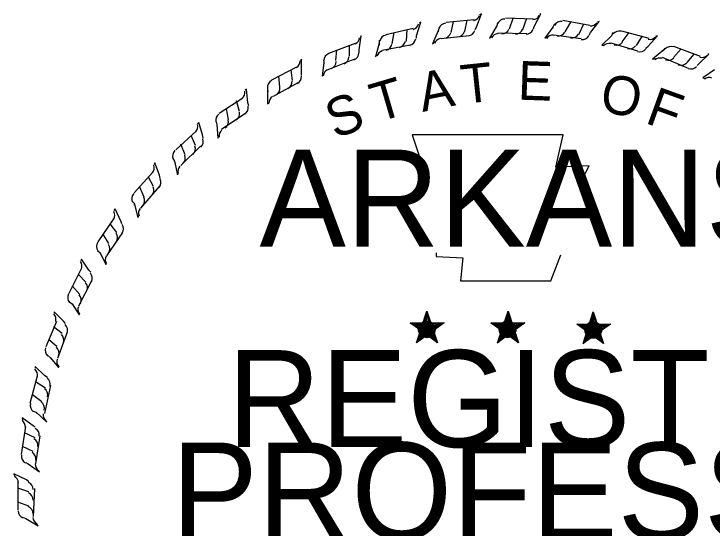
# Model space of a CAD drawing. Extents: x -900 to -62, y -12423 to -11428.
# Drawn here: x -141.81 to -114.78, y -12212.6 to -12192.71 of the extents above; entities that cross this region are included whole.
import ezdxf

# ---------------------------------------------------------------- set-up
doc = ezdxf.new("R2010")
doc.units = 0
doc.layers.add('Level 1', color=7, linetype='Continuous')

msp = doc.modelspace()

# ---------------------------------------------------------------- linework, layer by layer
at = {"layer": 'Level 1'}
for p, q in [((-123.902, -12193.218), (-123.71, -12192.714)), ((-123.71, -12192.714), (-123.782, -12192.762)), ((-121.67, -12193.194), (-121.406, -12192.714)), ((-121.406, -12192.714), (-121.454, -12192.738)), ((-125.078, -12193.026), (-123.998, -12192.93)), ((-124.886, -12193.434), (-124.79, -12193.002)), ((-124.358, -12193.386), (-124.262, -12192.954)), ((-122.774, -12192.858), (-121.694, -12192.906)), ((-122.63, -12193.29), (-122.486, -12192.882)), ((-122.102, -12193.314), (-121.958, -12192.882)), ((-120.566, -12192.954), (-119.51, -12193.146)), ((-119.486, -12193.434), (-119.15, -12193.002)), ((-119.15, -12193.002), (-119.222, -12193.026)), ((-127.406, -12193.506), (-126.35, -12193.266)), ((-126.23, -12193.554), (-126.062, -12193.026)), ((-126.062, -12193.026), (-126.11, -12193.074)), ((-125.342, -12193.242), (-125.39, -12193.362)), ((-123.95, -12193.314), (-123.902, -12193.218)), ((-123.11, -12193.17), (-123.398, -12193.65)), ((-123.11, -12193.17), (-123.134, -12193.194)), ((-123.086, -12193.05), (-123.11, -12193.17)), ((-121.694, -12193.29), (-121.67, -12193.194)), ((-120.95, -12193.218), (-121.262, -12193.65)), ((-120.878, -12193.098), (-120.95, -12193.218)), ((-120.95, -12193.218), (-120.95, -12193.266)), ((-120.47, -12193.41), (-120.254, -12193.026)), ((-119.942, -12193.506), (-119.75, -12193.098)), ((-127.166, -12193.866), (-127.094, -12193.434)), ((-126.614, -12193.77), (-126.59, -12193.314)), ((-125.39, -12193.362), (-125.606, -12193.866)), ((-125.39, -12193.362), (-125.39, -12193.41)), ((-121.958, -12193.482), (-123.062, -12193.458)), ((-119.846, -12193.674), (-120.926, -12193.53)), ((-119.534, -12193.53), (-119.486, -12193.434)), ((-118.622, -12193.434), (-118.67, -12193.554)), ((-118.286, -12193.362), (-117.23, -12193.65)), ((-118.262, -12193.794), (-117.998, -12193.434)), ((-128.438, -12194.106), (-128.366, -12193.554)), ((-128.366, -12193.554), (-128.39, -12193.626)), ((-127.67, -12193.722), (-127.67, -12193.842)), ((-126.23, -12193.65), (-126.23, -12193.554)), ((-125.606, -12193.866), (-125.51, -12193.794)), ((-124.19, -12193.554), (-125.27, -12193.674)), ((-123.398, -12193.65), (-123.302, -12193.578)), ((-121.262, -12193.65), (-121.19, -12193.602)), ((-118.67, -12193.554), (-119.054, -12193.914)), ((-118.67, -12193.554), (-118.694, -12193.554)), ((-117.71, -12193.938), (-117.47, -12193.554)), ((-117.254, -12193.962), (-116.894, -12193.554)), ((-116.894, -12193.554), (-116.966, -12193.578)), ((-129.614, -12194.226), (-128.582, -12193.842)), ((-128.822, -12194.346), (-128.822, -12193.914)), ((-127.67, -12193.842), (-127.814, -12194.37)), ((-127.67, -12193.842), (-127.67, -12193.914)), ((-126.47, -12193.914), (-127.55, -12194.13)), ((-119.054, -12193.914), (-118.958, -12193.914)), ((-117.662, -12194.154), (-118.694, -12193.842)), ((-117.35, -12194.034), (-117.254, -12193.962)), ((-116.606, -12194.034), (-116.654, -12194.106)), ((-116.27, -12193.962), (-115.238, -12194.346)), ((-116.27, -12194.394), (-115.982, -12194.058)), ((-129.35, -12194.514), (-129.302, -12194.106)), ((-128.438, -12194.202), (-128.438, -12194.106)), ((-127.814, -12194.37), (-127.742, -12194.274)), ((-116.654, -12194.106), (-117.086, -12194.466)), ((-116.654, -12194.106), (-116.702, -12194.154)), ((-115.742, -12194.586), (-115.478, -12194.274)), ((-115.286, -12194.634), (-114.902, -12194.274)), ((-114.902, -12194.274), (-114.95, -12194.274)), ((-130.67, -12194.466), (-130.718, -12194.514)), ((-130.67, -12194.994), (-130.67, -12194.466)), ((-129.806, -12194.586), (-129.878, -12195.114)), ((-129.83, -12194.49), (-129.806, -12194.586)), ((-129.806, -12194.586), (-129.83, -12194.634)), ((-128.63, -12194.466), (-129.662, -12194.874)), ((-117.086, -12194.466), (-116.99, -12194.442)), ((-115.694, -12194.826), (-116.702, -12194.394)), ((-131.822, -12195.258), (-130.862, -12194.754)), ((-131.03, -12195.282), (-131.078, -12194.874)), ((-115.358, -12194.706), (-115.286, -12194.634)), ((-114.686, -12194.874), (-115.142, -12195.186)), ((-131.51, -12195.546), (-131.558, -12195.114)), ((-130.67, -12195.09), (-130.67, -12194.994)), ((-129.878, -12195.114), (-129.83, -12195.066)), ((-130.814, -12195.378), (-131.774, -12195.906)), ((-115.142, -12195.186), (-115.046, -12195.21)), ((-132.806, -12195.618), (-132.854, -12195.666)), ((-132.758, -12196.146), (-132.806, -12195.618)), ((-131.99, -12195.546), (-131.99, -12195.666)), ((-131.99, -12195.666), (-131.99, -12196.194)), ((-131.99, -12195.666), (-131.966, -12195.714)), ((-133.862, -12196.554), (-132.95, -12195.954)), ((-133.07, -12196.482), (-133.19, -12196.074)), ((-132.71, -12196.266), (-132.758, -12196.146)), ((-131.99, -12196.194), (-131.942, -12196.146)), ((-133.502, -12196.794), (-133.574, -12196.386)), ((-132.83, -12196.554), (-133.766, -12197.178)), ((-134.654, -12196.914), (-134.702, -12196.962)), ((-134.51, -12197.394), (-134.654, -12196.914)), ((-133.982, -12196.89), (-133.958, -12196.986)), ((-133.958, -12196.986), (-133.91, -12197.514)), ((-133.958, -12196.986), (-133.958, -12197.034)), ((-135.542, -12197.97), (-134.75, -12197.25)), ((-134.774, -12197.802), (-134.942, -12197.418)), ((-134.486, -12197.514), (-134.51, -12197.394)), ((-133.91, -12197.514), (-133.862, -12197.418)), ((-135.182, -12198.162), (-135.35, -12197.754)), ((-134.582, -12197.826), (-135.35, -12198.57)), ((-135.662, -12198.306), (-135.59, -12198.402)), ((-135.59, -12198.402), (-135.47, -12198.93)), ((-135.59, -12198.402), (-135.59, -12198.45)), ((-136.358, -12198.474), (-136.382, -12198.546)), ((-136.166, -12198.954), (-136.358, -12198.474)), ((-137.15, -12199.626), (-136.43, -12198.834)), ((-135.47, -12198.93), (-135.446, -12198.834)), ((-136.406, -12199.386), (-136.598, -12199.026)), ((-136.142, -12199.074), (-136.166, -12198.954)), ((-136.766, -12199.794), (-136.934, -12199.41)), ((-136.19, -12199.386), (-136.91, -12200.226)), ((-137.222, -12199.962), (-137.15, -12200.034)), ((-137.894, -12200.25), (-137.942, -12200.322)), ((-137.654, -12200.754), (-137.894, -12200.25)), ((-137.15, -12200.034), (-137.006, -12200.586)), ((-137.15, -12200.034), (-137.15, -12200.106)), ((-137.006, -12200.586), (-136.958, -12200.49)), ((-138.542, -12201.522), (-137.942, -12200.634)), ((-137.822, -12201.162), (-138.086, -12200.826)), ((-137.63, -12200.826), (-137.654, -12200.754)), ((-138.134, -12201.594), (-138.35, -12201.234)), ((-137.606, -12201.162), (-138.23, -12202.074)), ((-138.566, -12201.858), (-138.47, -12201.954)), ((-139.19, -12202.194), (-139.214, -12202.266)), ((-138.902, -12202.626), (-139.19, -12202.194)), ((-138.47, -12201.954), (-138.254, -12202.41)), ((-138.47, -12201.954), (-138.47, -12201.978)), ((-138.254, -12202.41), (-138.23, -12202.314)), ((-139.67, -12203.514), (-139.19, -12202.554)), ((-138.83, -12202.698), (-138.902, -12202.626)), ((-139.022, -12203.082), (-139.31, -12202.794)), ((-139.262, -12203.562), (-139.55, -12203.226)), ((-138.806, -12203.034), (-139.31, -12204.018)), ((-139.67, -12203.85), (-139.55, -12203.922)), ((-139.55, -12203.922), (-139.286, -12204.354)), ((-139.55, -12203.922), (-139.55, -12203.97)), ((-139.886, -12204.594), (-140.246, -12204.234)), ((-140.246, -12204.234), (-140.246, -12204.306)), ((-139.286, -12204.354), (-139.262, -12204.282)), ((-125.822, -12204.21), (-125.918, -12204.666)), ((-125.822, -12204.21), (-125.87, -12204.666)), ((-125.822, -12204.21), (-125.846, -12204.666)), ((-125.822, -12204.882), (-125.822, -12204.21)), ((-125.822, -12204.21), (-125.702, -12204.666)), ((-125.822, -12204.21), (-125.726, -12204.666)), ((-125.822, -12204.21), (-125.75, -12204.666)), ((-122.678, -12204.21), (-122.798, -12204.666)), ((-122.678, -12204.21), (-122.75, -12204.666)), ((-122.678, -12204.21), (-122.726, -12204.666)), ((-122.678, -12204.882), (-122.678, -12204.21)), ((-122.678, -12204.21), (-122.558, -12204.666)), ((-122.678, -12204.21), (-122.582, -12204.666)), ((-122.678, -12204.21), (-122.63, -12204.666)), ((-119.39, -12204.234), (-119.486, -12204.69)), ((-119.39, -12204.234), (-119.462, -12204.69)), ((-119.39, -12204.906), (-119.39, -12204.234)), ((-119.39, -12204.234), (-119.246, -12204.69)), ((-119.39, -12204.234), (-119.27, -12204.69)), ((-119.39, -12204.234), (-119.342, -12204.69)), ((-119.39, -12204.234), (-119.39, -12204.69)), ((-140.558, -12205.578), (-140.15, -12204.594)), ((-139.814, -12204.69), (-139.886, -12204.594)), ((-139.934, -12205.074), (-140.27, -12204.81)), ((-126.47, -12204.666), (-125.822, -12204.882)), ((-126.47, -12204.666), (-125.99, -12204.714)), ((-126.47, -12204.666), (-125.99, -12204.762)), ((-126.47, -12204.666), (-125.99, -12204.786)), ((-126.47, -12204.666), (-126.014, -12204.858)), ((-126.47, -12204.666), (-126.014, -12204.906)), ((-126.47, -12204.666), (-126.014, -12204.954)), ((-126.23, -12205.434), (-125.822, -12204.882)), ((-125.15, -12204.666), (-125.822, -12204.882)), ((-125.414, -12205.434), (-125.822, -12204.882)), ((-125.15, -12204.666), (-125.75, -12204.714)), ((-125.15, -12204.666), (-125.702, -12204.786)), ((-125.15, -12204.666), (-125.702, -12204.81)), ((-125.15, -12204.666), (-125.582, -12204.834)), ((-125.15, -12204.666), (-125.534, -12204.858)), ((-125.15, -12204.666), (-125.51, -12204.906)), ((-123.35, -12204.666), (-122.678, -12204.882)), ((-123.35, -12204.666), (-122.87, -12204.714)), ((-123.35, -12204.666), (-122.87, -12204.762)), ((-123.35, -12204.666), (-122.87, -12204.786)), ((-123.35, -12204.666), (-122.87, -12204.858)), ((-123.35, -12204.666), (-122.894, -12204.906)), ((-123.35, -12204.666), (-122.894, -12204.954)), ((-123.086, -12205.434), (-122.678, -12204.882)), ((-122.03, -12204.666), (-122.678, -12204.882)), ((-122.27, -12205.434), (-122.678, -12204.882)), ((-122.03, -12204.666), (-122.606, -12204.714)), ((-122.03, -12204.666), (-122.582, -12204.786)), ((-122.03, -12204.666), (-122.582, -12204.81)), ((-122.03, -12204.666), (-122.462, -12204.834)), ((-122.03, -12204.666), (-122.414, -12204.858)), ((-122.03, -12204.666), (-122.39, -12204.906)), ((-120.014, -12204.714), (-119.39, -12204.906)), ((-120.014, -12204.714), (-119.534, -12204.738)), ((-120.014, -12204.714), (-119.534, -12204.786)), ((-120.014, -12204.714), (-119.582, -12204.834)), ((-120.014, -12204.714), (-119.582, -12204.882)), ((-120.014, -12204.714), (-119.582, -12204.93)), ((-120.014, -12204.714), (-119.582, -12204.954)), ((-118.718, -12204.714), (-119.39, -12204.906)), ((-118.718, -12204.714), (-119.294, -12204.738)), ((-118.718, -12204.714), (-119.27, -12204.786)), ((-118.718, -12204.714), (-119.27, -12204.834)), ((-118.718, -12204.714), (-119.15, -12204.858)), ((-118.718, -12204.714), (-119.102, -12204.906)), ((-118.718, -12204.714), (-119.078, -12204.906)), ((-139.742, -12205.026), (-140.126, -12206.034)), ((-126.23, -12205.434), (-125.99, -12204.93)), ((-126.23, -12205.434), (-125.99, -12204.978)), ((-126.23, -12205.434), (-125.942, -12205.002)), ((-126.23, -12205.434), (-125.822, -12205.026)), ((-126.23, -12205.434), (-125.87, -12205.05)), ((-126.23, -12205.434), (-125.822, -12205.074)), ((-125.414, -12205.434), (-125.822, -12205.05)), ((-125.414, -12205.434), (-125.822, -12205.074)), ((-125.414, -12205.434), (-125.75, -12205.05)), ((-125.414, -12205.434), (-125.702, -12204.978)), ((-125.414, -12205.434), (-125.678, -12204.906)), ((-125.414, -12205.434), (-125.63, -12204.906)), ((-123.086, -12205.434), (-122.87, -12204.93)), ((-123.086, -12205.434), (-122.87, -12204.978)), ((-123.086, -12205.434), (-122.822, -12205.002)), ((-123.086, -12205.434), (-122.702, -12205.026)), ((-123.086, -12205.434), (-122.75, -12205.05)), ((-123.086, -12205.434), (-122.678, -12205.074)), ((-122.27, -12205.434), (-122.702, -12205.05)), ((-122.27, -12205.434), (-122.702, -12205.074)), ((-122.27, -12205.434), (-122.63, -12205.05)), ((-122.27, -12205.434), (-122.558, -12204.978)), ((-122.27, -12205.434), (-122.534, -12204.906)), ((-122.27, -12205.434), (-122.51, -12204.906)), ((-119.774, -12205.458), (-119.39, -12204.906)), ((-119.774, -12205.458), (-119.582, -12204.954)), ((-119.774, -12205.458), (-119.534, -12205.002)), ((-119.774, -12205.458), (-119.51, -12205.026)), ((-119.774, -12205.458), (-119.462, -12205.074)), ((-119.774, -12205.458), (-119.39, -12205.074)), ((-119.774, -12205.458), (-119.366, -12205.098)), ((-118.982, -12205.458), (-119.39, -12204.906)), ((-118.982, -12205.458), (-119.39, -12205.074)), ((-118.982, -12205.458), (-119.39, -12205.122)), ((-118.982, -12205.458), (-119.294, -12205.074)), ((-118.982, -12205.458), (-119.246, -12205.002)), ((-118.982, -12205.458), (-119.222, -12204.93)), ((-118.982, -12205.458), (-119.174, -12204.906)), ((-140.15, -12205.578), (-140.462, -12205.314)), ((-140.51, -12205.914), (-140.39, -12206.01)), ((-140.39, -12206.01), (-140.078, -12206.394)), ((-140.39, -12206.01), (-140.39, -12206.034)), ((-140.606, -12206.706), (-140.99, -12206.346)), ((-140.99, -12206.346), (-140.99, -12206.418)), ((-140.078, -12206.394), (-140.054, -12206.322)), ((-141.182, -12207.762), (-140.894, -12206.706)), ((-140.51, -12206.778), (-140.606, -12206.706)), ((-140.582, -12207.186), (-140.966, -12206.946)), ((-140.39, -12207.09), (-140.63, -12208.17)), ((-140.726, -12207.714), (-141.086, -12207.45)), ((-141.062, -12208.074), (-140.942, -12208.122)), ((-140.942, -12208.122), (-140.534, -12208.506)), ((-140.942, -12208.122), (-140.918, -12208.17)), ((-141.062, -12208.65), (-141.494, -12208.338)), ((-141.494, -12208.338), (-141.47, -12208.434)), ((-140.534, -12208.506), (-140.582, -12208.41)), ((-141.518, -12209.754), (-141.35, -12208.674)), ((-140.99, -12208.698), (-141.062, -12208.65)), ((-140.99, -12209.106), (-141.398, -12208.914)), ((-140.798, -12209.034), (-140.966, -12210.114)), ((-141.062, -12209.634), (-141.47, -12209.442)), ((-141.35, -12210.066), (-141.254, -12210.114)), ((-141.254, -12210.114), (-140.822, -12210.426)), ((-141.254, -12210.114), (-141.23, -12210.114)), ((-141.326, -12210.738), (-141.806, -12210.498)), ((-141.806, -12210.498), (-141.782, -12210.57)), ((-140.822, -12210.426), (-140.87, -12210.354)), ((-141.638, -12211.89), (-141.638, -12210.81)), ((-141.23, -12210.81), (-141.326, -12210.738)), ((-141.23, -12211.194), (-141.614, -12211.074)), ((-141.014, -12211.074), (-141.062, -12212.154)), ((-141.23, -12211.746), (-141.662, -12211.602)), ((-141.47, -12212.178), (-141.35, -12212.226)), ((-141.35, -12212.226), (-140.87, -12212.514)), ((-141.35, -12212.226), (-141.302, -12212.25)), ((-140.87, -12212.514), (-140.942, -12212.418))]:
    msp.add_line(p, q, dxfattribs=at)
for points in [[(-126.398, -12197.394), (-125.87, -12198.954)], [(-119.822, -12199.146), (-119.534, -12198.594), (-120.83, -12198.642), (-120.542, -12197.394), (-126.398, -12197.394)], [(-125.462, -12201.954), (-125.462, -12202.098), (-124.43, -12202.146), (-124.526, -12203.034), (-121.022, -12203.034), (-120.638, -12202.026)], [(-125.822, -12204.21), (-125.414, -12205.434), (-126.47, -12204.666), (-125.15, -12204.666), (-126.23, -12205.434), (-125.822, -12204.21)], [(-122.678, -12204.21), (-122.27, -12205.434), (-123.35, -12204.666), (-122.03, -12204.666), (-123.086, -12205.434), (-122.678, -12204.21)], [(-119.39, -12204.234), (-118.982, -12205.458), (-120.014, -12204.714), (-118.718, -12204.714), (-119.774, -12205.458), (-119.39, -12204.234)]]:
    msp.add_lwpolyline(points, dxfattribs=at)
for centre, radius in [((-125.827, -12204.913), 0.323), ((-125.827, -12204.913), 0.292), ((-122.697, -12204.913), 0.323), ((-122.697, -12204.913), 0.292), ((-119.384, -12204.935), 0.323), ((-125.827, -12204.913), 0.271), ((-125.827, -12204.913), 0.249), ((-125.827, -12204.913), 0.217), ((-125.827, -12204.913), 0.202), ((-125.827, -12204.913), 0.186), ((-125.827, -12204.913), 0.16), ((-125.827, -12204.913), 0.14), ((-125.827, -12204.913), 0.117), ((-125.827, -12204.913), 0.0929), ((-125.827, -12204.913), 0.0693), ((-125.827, -12204.913), 0.0556), ((-125.827, -12204.913), 0.027), ((-122.697, -12204.913), 0.271), ((-122.697, -12204.913), 0.249), ((-122.697, -12204.913), 0.217), ((-122.697, -12204.913), 0.202), ((-122.697, -12204.913), 0.186), ((-122.697, -12204.913), 0.16), ((-122.697, -12204.913), 0.14), ((-122.697, -12204.913), 0.117), ((-122.697, -12204.913), 0.0929), ((-122.697, -12204.913), 0.0693), ((-122.697, -12204.913), 0.0556), ((-122.697, -12204.913), 0.027), ((-119.384, -12204.935), 0.292), ((-119.384, -12204.935), 0.271), ((-119.384, -12204.935), 0.249), ((-119.384, -12204.935), 0.217), ((-119.384, -12204.935), 0.202), ((-119.384, -12204.935), 0.186), ((-119.384, -12204.935), 0.16), ((-119.384, -12204.935), 0.14), ((-119.384, -12204.935), 0.117), ((-119.384, -12204.935), 0.0929), ((-119.384, -12204.935), 0.0693), ((-119.384, -12204.935), 0.0556), ((-119.384, -12204.935), 0.027)]:
    msp.add_circle(centre, radius, dxfattribs=at)
for centre, start, end in [((-124.066, -12192.675), 279.9249, 338.7128), ((-122.806, -12193.205), 89.1628, 157.5368), ((-121.733, -12192.634), 273.4236, 332.2115), ((-120.626, -12193.303), 81.4231, 149.797), ((-126.431, -12193.024), 286.2701, 345.0579), ((-125.068, -12193.363), 95.6641, 164.0381), ((-119.485, -12192.882), 265.6839, 324.4717), ((-127.351, -12193.819), 102.0093, 170.3832), ((-125.183, -12193.358), 275.6641, 344.0381), ((-124.657, -12193.307), 275.6641, 344.0381), ((-124.248, -12193.266), 275.6641, 344.0381), ((-123.055, -12193.771), 93.4236, 152.2115), ((-122.92, -12193.186), 269.1628, 337.5368), ((-122.392, -12193.196), 269.1628, 337.5368), ((-121.981, -12193.2), 269.1628, 337.5368), ((-120.948, -12193.83), 85.6839, 144.4717), ((-120.736, -12193.269), 261.4231, 329.797), ((-120.214, -12193.35), 261.4231, 329.797), ((-118.38, -12193.669), 73.9909, 142.3649), ((-128.725, -12193.6), 294.8371, 353.6249), ((-126.948, -12193.718), 282.0093, 350.3832), ((-126.547, -12193.631), 282.0093, 350.3832), ((-125.25, -12193.954), 99.9249, 158.7128), ((-119.807, -12193.41), 261.4231, 329.797), ((-118.485, -12193.621), 253.9909, 322.3649), ((-117.195, -12193.4), 258.2517, 317.0395), ((-127.466, -12193.826), 282.0093, 350.3832), ((-118.768, -12194.15), 78.2517, 137.0395), ((-117.977, -12193.769), 253.9909, 322.3649), ((-117.582, -12193.881), 253.9909, 322.3649), ((-116.377, -12194.267), 69.0955, 137.4695), ((-129.516, -12194.523), 110.5763, 178.9503), ((-128.749, -12194.217), 290.5763, 358.9503), ((-127.467, -12194.426), 106.2701, 165.0579), ((-115.173, -12194.099), 253.3563, 312.1441), ((-131.026, -12194.531), 301.9545, 0.7423), ((-129.629, -12194.547), 290.5763, 358.9503), ((-129.133, -12194.363), 290.5763, 358.9503), ((-116.804, -12194.713), 73.3563, 132.1441), ((-116.477, -12194.21), 249.0955, 317.4695), ((-115.984, -12194.401), 249.0955, 317.4695), ((-129.54, -12195.14), 114.8371, 173.6249), ((-115.6, -12194.546), 249.0955, 317.4695), ((-130.974, -12195.147), 297.6937, 6.0677), ((-131.697, -12195.545), 117.6937, 186.0677), ((-131.337, -12195.339), 297.6937, 6.0677), ((-114.901, -12195.47), 67.3316, 126.1194), ((-133.161, -12195.741), 309.1135, 7.9014), ((-131.806, -12195.583), 297.6937, 6.0677), ((-131.645, -12196.161), 121.9545, 180.7423), ((-133.368, -12196.581), 304.8528, 13.2267), ((-133.032, -12196.345), 304.8528, 13.2267), ((-133.7, -12196.83), 124.8528, 193.2267), ((-134.985, -12197.067), 316.8235, 15.6113), ((-133.803, -12196.881), 304.8528, 13.2267), ((-133.571, -12197.435), 129.1135, 187.9014), ((-134.776, -12197.649), 312.5627, 20.9367), ((-135.078, -12197.927), 312.5627, 20.9367), ((-135.373, -12198.219), 132.5627, 200.9367), ((-135.469, -12198.283), 312.5627, 20.9367), ((-136.673, -12198.673), 322.2653, 21.0531), ((-135.164, -12198.801), 136.8235, 195.6113), ((-136.411, -12199.233), 318.0045, 26.3785), ((-136.684, -12199.539), 318.0045, 26.3785), ((-136.951, -12199.857), 138.0045, 206.3785), ((-137.04, -12199.93), 318.0045, 26.3785), ((-136.688, -12200.416), 142.2653, 201.0531), ((-138.198, -12200.5), 329.9636, 28.7515), ((-137.863, -12201.019), 325.7028, 34.0768), ((-138.093, -12201.359), 325.7028, 34.0768), ((-138.314, -12201.71), 145.7028, 214.0768), ((-138.393, -12201.795), 325.7028, 34.0768), ((-137.979, -12202.229), 149.9636, 208.7515), ((-139.47, -12202.464), 337.2243, 36.0121), ((-139.071, -12202.936), 332.9635, 41.3375), ((-139.257, -12203.303), 332.9635, 41.3375), ((-139.432, -12203.679), 152.9635, 221.3375), ((-139.499, -12203.773), 332.9635, 41.3375), ((-139.034, -12204.151), 157.2243, 216.0121), ((-140.475, -12204.522), 343.6465, 42.4343), ((-140.026, -12204.947), 339.3857, 47.7597), ((-140.17, -12205.332), 339.3857, 47.7597), ((-140.302, -12205.726), 159.3857, 227.7597), ((-140.358, -12205.826), 339.3857, 47.7597), ((-139.853, -12206.151), 163.6465, 222.4343), ((-141.192, -12206.682), 350.445, 49.2329), ((-140.697, -12207.051), 346.1842, 54.5582), ((-140.793, -12207.45), 346.1842, 54.5582), ((-140.878, -12207.856), 166.1842, 234.5582), ((-140.922, -12207.963), 346.1842, 54.5582), ((-140.382, -12208.225), 170.445, 229.2329), ((-141.658, -12208.688), 356.646, 55.4338), ((-141.125, -12209.001), 352.3852, 60.7592), ((-141.178, -12209.409), 352.3852, 60.7592), ((-141.25, -12209.932), 352.3852, 60.7592), ((-141.218, -12209.821), 172.3852, 240.7592), ((-140.685, -12210.135), 176.646, 235.4338), ((-141.926, -12210.863), 3.9474, 62.7352), ((-141.357, -12211.106), 359.6866, 68.0606), ((-141.358, -12211.517), 359.6866, 68.0606), ((-141.363, -12212.045), 359.6866, 68.0606), ((-141.346, -12211.931), 179.6866, 248.0606), ((-140.777, -12212.174), 183.9474, 242.7352)]:
    msp.add_arc(centre, 0.296, start, end, dxfattribs=at)

# ---------------------------------------------------------------- texts
for s, height, rotation, p in [('T', 1.5, 6.0228, (-124.43, -12196.194)), ('E', 1.5, 358.0732, (-122.318, -12196.026)), ('A', 1.499, 11.2132, (-125.99, -12196.506)), ('T', 1.5, 16.4036, (-127.742, -12196.914)), ('O', 1.499, 350.4515, (-119.174, -12196.482)), ('F', 1.499, 340.0707, (-117.422, -12196.914)), ('S', 1.5, 21.594, (-129.374, -12197.562))]:
    msp.add_text(s, height=height, rotation=rotation, dxfattribs=at).set_placement(p)
for s, height, p in [('ARKANSAS', 3.7498, (-132.302, -12201.714)), ('REGISTERED', 3.7498, (-133.55, -12209.466)), ('PROFESSIONAL', 3.74976, (-135.71, -12213.042))]:
    msp.add_text(s, height=height, dxfattribs=at).set_placement(p)

doc.saveas('drawing.dxf')
